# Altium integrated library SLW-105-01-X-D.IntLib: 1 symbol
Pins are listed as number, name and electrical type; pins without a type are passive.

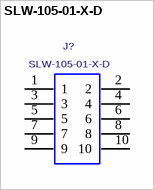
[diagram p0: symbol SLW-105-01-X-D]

## SLW-105-01-X-D
designator J?
LOW PROFILE, DOUBLE ROW, 0.100"SOCKET STRIP ASSEMBLY.; MANUFACTURER: SAMTEC
footprint SLW-105-01-X-D
pins: 1, 2, 3, 4, 5, 6, 7, 8, 9, 10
